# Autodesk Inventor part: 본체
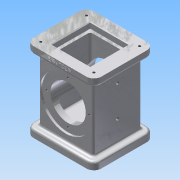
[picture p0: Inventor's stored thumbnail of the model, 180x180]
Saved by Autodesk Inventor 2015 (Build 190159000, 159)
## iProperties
Created: 2017-08
Part Number: 본체
Material: 알루미늄 6061
Document SubType Name: Modeling
Designer: Administrator
Density: 2.7 g/cm^3
Appearance: 알루미늄 - 평지
Author: Administrator
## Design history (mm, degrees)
sketch "스케치1"
  geometry: L1 (37, -33)-(-37, -33); L2 (-37, -33)-(-37, 33); L3 (-37, 33)-(37, 33); L4 (37, 33)-(37, -33); 1 further point
  constraints: 8 end point, 2 parallel, 1 horizontal, 1 perpendicular
  dimensions: "d0" = 37 distance from line of point (0, 0) L4; "d1" = 74 distance between parallel lines of L2 L4; "d2" = 66 distance between parallel lines of L3 L1; "d3" = 33 distance from line of point (0, 0) L1
extrude "돌출1" new body sketch "스케치1" distance "d4" = 108; taper "d5" = 0 deg
sketch "스케치2"
  geometry: L1 (-46, 41)-(46, 41); L2 (46, 41)-(46, -41); L3 (46, -41)-(-46, -41); L4 (-46, -41)-(-46, 41); 1 further point
  constraints: 8 end point, 2 parallel, 1 horizontal, 1 perpendicular
  dimensions: "d6" = 46 distance from line of point (0, 0) L4; "d7" = 92 distance between parallel lines of L2 L4; "d8" = 41 distance from line of point (0, 0) L1; "d9" = 82 distance between parallel lines of L3 L1
extrude "돌출2" join sketch "스케치2" distance "d10" = 10; taper "d11" = 0 deg
node "작업 평면1"
sketch "스케치3"
  geometry: L1 (-26, -26)-(26, -26); L2 (26, -26)-(26, 26); L3 (26, 26)-(-26, 26); L4 (-26, 26)-(-26, -26); L5 (-26, -26)-(26, 26); L6 (26, -26)-(-26, 26); 1 further point
  constraints: 12 end point, 2 midpoint, 2 parallel, 1 horizontal, 1 perpendicular
  dimensions: "d12" = 52 distance of L2.end L3.end; "d13" = 52 distance between parallel lines of L1 L3
extrude "돌출3" cut sketch "스케치3" distance "d14" = 8; taper "d15" = 0 deg
sketch "스케치4"
  geometry: L1 (22, -22)-(-22, -22); L2 (-22, -22)-(-22, 22); L3 (-22, 22)-(22, 22); L4 (22, 22)-(22, -22); L5 (22, -22)-(-22, 22); L6 (-22, -22)-(22, 22); 1 further point
  constraints: 12 end point, 2 midpoint, 2 parallel, 1 horizontal, 1 perpendicular
  dimensions: "d16" = 44 distance of L2.end L3.end; "d17" = 44 distance of L1.end L2.end
extrude "돌출4" cut sketch "스케치4" distance "d18" = 74; taper "d19" = 0 deg
sketch "스케치5"
  geometry: L1 (24, -24)-(-24, -24); L2 (-24, -24)-(-24, 24); L3 (-24, 24)-(24, 24); L4 (24, 24)-(24, -24); L5 (24, -24)-(-24, 24); L6 (-24, -24)-(24, 24); 1 further point
  constraints: 12 end point, 2 midpoint, 2 parallel, 1 horizontal, 1 perpendicular
  dimensions: "d20" = 48 distance of L2.end L3.end; "d21" = 48 distance of L3.end L1.start
extrude "돌출5" cut sketch "스케치5" distance "d22" = 16; taper "d23" = 0 deg
sketch "스케치6"
  geometry: L1 (83, -98)-(-9, -98) reference; C1 r 35 at (37, -44); 2 further points
  constraints: 1 centre point, 1 midpoint, 1 vertical alignment
  dimensions: "d24" = 70 diameter of C1; "d25" = 54 distance from line of L1 C1.centre
extrude "돌출6" cut sketch "스케치6" distance "d26" = 3; taper "d27" = 0 deg
sketch "스케치7"
  geometry: L1 (46, 54)-(-46, 54) reference; C1 r 24 at (0, 0); 2 further points
  constraints: 1 centre point, 1 midpoint, 1 vertical alignment
  dimensions: "d28" = 48 diameter of C1
extrude "돌출7" cut sketch "스케치7" stored distance "d29" = 3; taper "d30" = 0 deg
sketch "스케치8"
  geometry: L1 (83, 0)-(74, 0) reference; L2 (74, 0)-(0, 0) reference; L3 (0, -88)-(0, 0) reference; L4 (0, -88)-(74, -88) reference; L5 (74, 0)-(74, -88) reference; L6 (83, 10)-(83, 0) reference; L7 (-9, 10)-(83, 10) reference; L8 (-9, 0)-(-9, 10) reference; L9 (0, 0)-(-9, 0) reference; L10 (-9, -88)-(0, -88) reference; L11 (-9, -98)-(-9, -88) reference; L12 (83, -98)-(-9, -98) reference; L13 (83, -88)-(83, -98) reference; L14 (74, -88)-(83, -88) reference; C1 r 24 at (37, -44) reference; C2 r 35 at (37, -44); 1 further point
  constraints: 1 centre point, 1 coincident
  dimensions: "d31" = 70 diameter of C2
extrude "돌출8" cut sketch "스케치8" distance "d32" = 3; taper "d33" = 0 deg
fillet "모깎기1" dims "d34" = 10
fillet "모깎기2" dims "d35" = 3
fillet "모깎기3" dims "d36" = 3
fillet "모깎기4" dims "d37" = 3
fillet "모깎기5" dims "d38" = 3
sketch "스케치9" dims "d39" = 58
  geometry: L1 (36, 54)-(-36, 54) reference; L2 (-37, 41)-(-37, -41) reference; 6 further points
  constraints: 3 midpoint, 3 vertical alignment, 1 horizontal alignment, 2 other
hole "구멍1" sketch "스케치9" at (0, 29) diameter "d40" = 3.242; stored, may be unused: countersink angle "d44" = 90 deg, drill point angle "d46" = 118 deg; dims "d41" = 4, "d42" = 4, "d43" = 2, "d45" = 6
sketch "스케치10"
  geometry: L1 (-46, -31)-(-46, 31) reference; L2 (-36, 41)-(36, 41) reference; L3 (46, 31)-(46, -31) reference; L4 (36, -41)-(-36, -41) reference; L5 (26, -26)-(26, 26) reference; L6 (26, 26)-(-26, 26) reference; L7 (-26, 26)-(-26, -26) reference; L8 (-26, -26)-(26, -26) reference; A1 r 10 centre (-36, -31) between (-46, -31) and (-36, -41) reference; A2 r 10 centre (-36, 31) between (-36, 41) and (-46, 31) reference; A3 r 10 centre (36, 31) between (46, 31) and (36, 41) reference; A4 r 10 centre (36, -31) between (36, -41) and (46, -31) reference; 5 further points
  constraints: 4 coincident
hole "구멍2" sketch "스케치10" at (-36, 31), (-36, -31), (36, -31), (36, 31) diameter "d50" = 3.242; stored, may be unused: countersink angle "d54" = 90 deg, drill point angle "d56" = 118 deg; dims "d51" = 4, "d52" = 4, "d53" = 2, "d55" = 6
sketch "스케치11"
  geometry: L1 (60, 0)-(0, 0) reference; L2 (65.196, -3)-(67.928, -3) reference; L3 (70.95, -6)-(70.95, -13) reference; L4 (70.95, -13)-(62.276, -13) reference; L5 (62.276, -13)-(62.276, -7) reference; L6 (59.724, -7)-(59.724, -13) reference; L7 (59.724, -13)-(0.276, -13) reference; L8 (0.276, -13)-(0.276, -7) reference; L9 (-2.276, -7)-(-2.276, -13) reference; L10 (-2.276, -13)-(-10.95, -13) reference; L11 (-10.95, -13)-(-10.95, -6) reference; L12 (-7.928, -3)-(-5.196, -3) reference; L13 (0, 0)-(0, 82) reference; L14 (-5.196, 85)-(-7.928, 85) reference; L15 (-10.95, 88)-(-10.95, 95) reference; L16 (-10.95, 95)-(-2.276, 95) reference; L17 (-2.276, 95)-(-2.276, 89) reference; L18 (0.276, 89)-(0.276, 95) reference; L19 (0.276, 95)-(59.724, 95) reference; L20 (59.724, 95)-(59.724, 89) reference; L21 (62.276, 89)-(62.276, 95) reference; L22 (62.276, 95)-(70.95, 95) reference; L23 (70.95, 95)-(70.95, 88) reference; L24 (67.928, 85)-(65.196, 85) reference; L25 (60, 0)-(60, 82) reference; L26 (0, 82)-(60, 82) reference; L27 (61, 95)-(-1, 95) reference; L28 (61, -13)-(-1, -13) reference; 5 further points
  constraints: 4 horizontal alignment, 2 midpoint, 2 vertical alignment, 8 other
  dimensions: "d57" = 38 distance from line of point (30, 25) L7; "d58" = 42 distance of point (30, 67) point (30, 25)
hole "구멍3" sketch "스케치11" at (30, 67), (30, 25) diameter "d59" = 4.134; stored, may be unused: countersink angle "d63" = 90 deg, drill point angle "d65" = 118 deg; dims "d60" = 20, "d61" = 4, "d62" = 2, "d64" = 24.2
node "작업 평면2"
sketch "스케치12"
  geometry: L1 (5.36, -14.666)-(66.64, -14.666); L2 (66.64, -14.666)-(66.64, 6.666); L3 (66.64, 6.666)-(5.36, 6.666); L4 (5.36, 6.666)-(5.36, -14.666); L5 (72, -7)-(0, -7) reference; L6 (72, 0)-(72, -7) reference; L7 (72, 0)-(0, 0) reference; L8 (0, -7)-(0, 0) reference; L9 (-10, 0)-(-10, -7) reference; L10 (72, 0)-(82, 0) reference; 4 further points
  constraints: 2 midpoint, 1 horizontal alignment, 1 vertical alignment, 2 other
  dimensions: "d67" = 46 distance from line of point (36, -4) L9; "d68" = 4 distance from line of L10 point (36, -4)
feature "엠보싱1" sketch "스케치12" dims "d0" = 37, "d1" = 74, "d2" = 66, "d3" = 33, "d69" = 0.5, "d70" = 0
chamfer "모따기1" distance "d71" = 1; stored, may be unused: second distance "d72" = 2, angle "d73" = 45 deg
fillet "모깎기6" dims "d74" = 3
fillet "모깎기7" dims "d75" = 3
node "솔리드1"
mirror "대칭1"
pattern_circular "원형 패턴1" dims angle "d48" = 360 deg
mirror "대칭2"
mirror "대칭3"
node "투영된 루프1"
node "절단 모서리 투영1"
node "절단 모서리 투영2"
node "절단 모서리 투영3"
other parameters: "d66" = 2
